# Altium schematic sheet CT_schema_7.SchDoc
size 252 x 159 mm
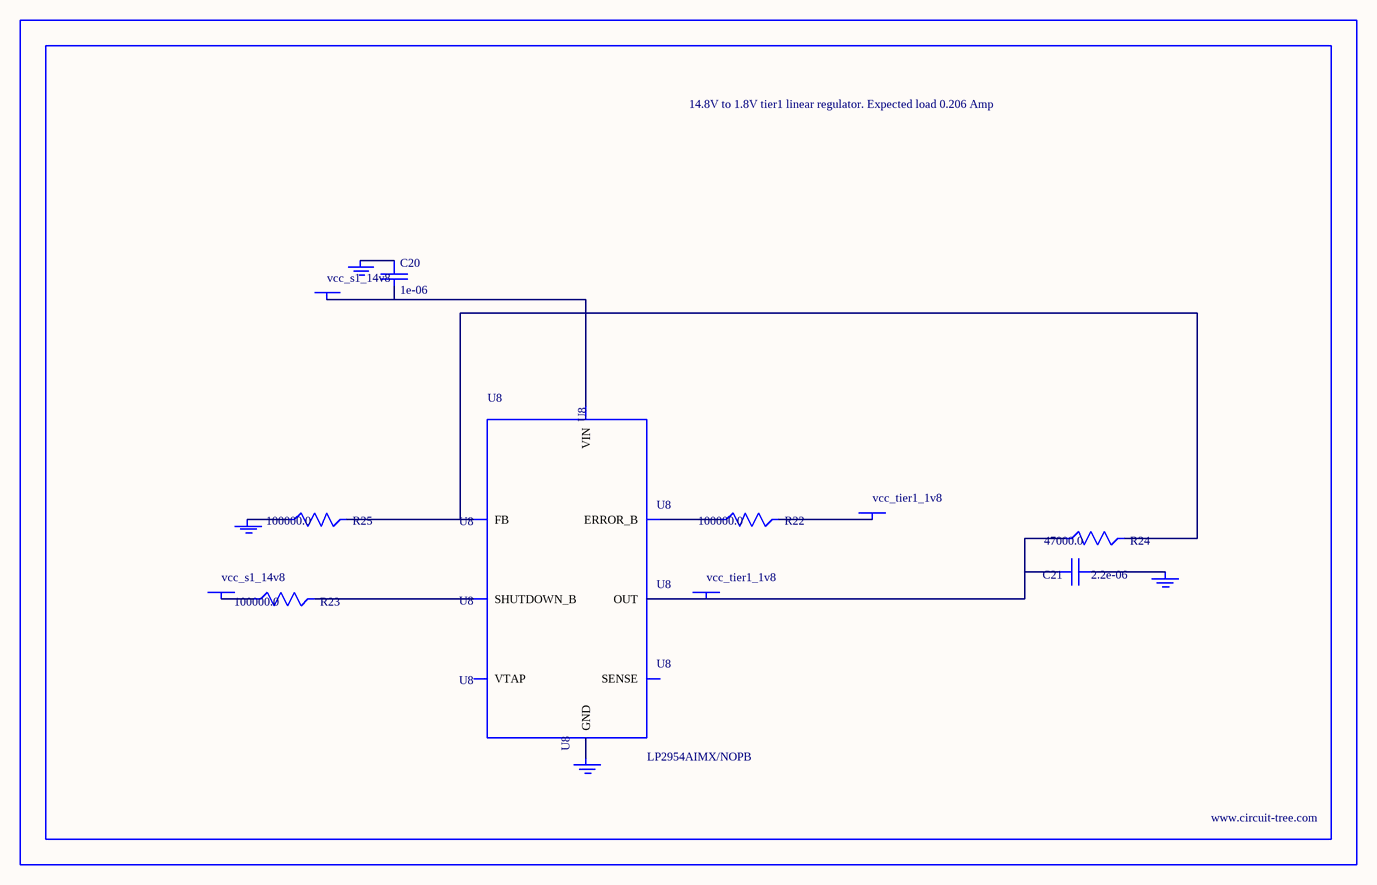
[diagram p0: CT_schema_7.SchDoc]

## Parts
BORDER6  (no value)
C20  1e-06  [EXV-9B]
C21  2.2e-06  [EXV-9B]
GND_INSTANCE_6_0  (no value)
GND_INSTANCE_6_1  (no value)
GND_INSTANCE_6_2  (no value)
GND_INSTANCE_6_3  (no value)
POWER_INSTANCE_6_0  vcc_s1_14v8
POWER_INSTANCE_6_1  vcc_tier1_1v8
POWER_INSTANCE_6_2  vcc_s1_14v8
POWER_INSTANCE_6_3  vcc_tier1_1v8
R22  100000.0  [R0603]
R23  100000.0  [R0603]
R24  47000.0  [R0603]
R25  100000.0  [R0603]
U8  LP2954AIMX/NOPB  [LP2954]

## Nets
NetC20_1: C20.1 GND_INSTANCE_6_2.0(GND)
NetC20_2: C20.2 POWER_INSTANCE_6_2.0(PWR) U8.8(VIN)
NetC21_1: C21.1 GND_INSTANCE_6_0.0(GND)
NetC21_2: C21.2 POWER_INSTANCE_6_3.0(PWR) R24.1 U8.1(OUT)
NetGND_INSTANCE_6_1_0: GND_INSTANCE_6_1.0(GND) R25.1
NetGND_INSTANCE_6_3_0: GND_INSTANCE_6_3.0(GND) U8.4(GND)
NetPOWER_INSTANCE_6_0_0: POWER_INSTANCE_6_0.0(PWR) R23.1
NetPOWER_INSTANCE_6_1_0: POWER_INSTANCE_6_1.0(PWR) R22.2
NetR22_1: R22.1 U8.5(ERROR_B)
NetR23_2: R23.2 U8.3(SHUTDOWN_B)
NetR24_2: R24.2 R25.2 U8.7(FB)

Not connected (* = marked no-connect by the designer): U8 2(SENSE) 6(VTAP)

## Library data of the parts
BORDER6 = BORDER_PAGE6
C20 = EDK105M050A9BAA
C21 = EDK225M050A9BAA
GND_INSTANCE_6_0-GND_INSTANCE_6_3 = GND
POWER_INSTANCE_6_0-POWER_INSTANCE_6_3 = PWR
R22 R23 R25 = RC0603JR-07100KL
R24 = RC0603JR-0747KL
